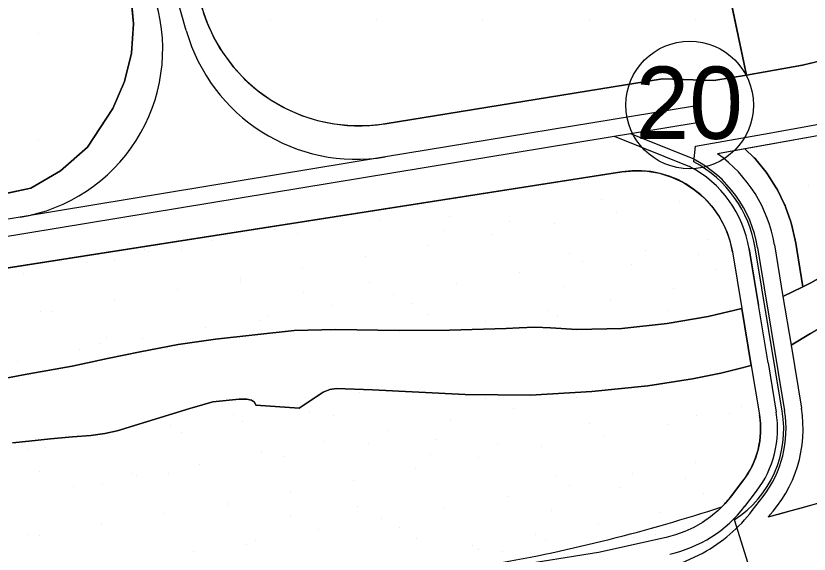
# Model space of a CAD drawing. Extents: x 419109 to 421295, y 4452223 to 4457798.
# Drawn here: x 420441.4 to 420628, y 4454862 to 4454988.5 of the extents above; entities that cross this region are included whole.
import ezdxf

# ---------------------------------------------------------------- set-up
doc = ezdxf.new("R2010")
doc.units = 0
for name, color, linetype in [('0_PLAN_ONAMA_İLAVE_SINIRI', 7, 'Continuous'), ('ADAKENARI', 7, 'Continuous'), ('Default', 7, 'Continuous'), ('KALDIRIM_FAT', 7, 'Continuous'), ('KD_DAIRE', 7, 'Continuous'), ('KD_YGEN', 7, 'Continuous'), ('PL_AYA_PARK_DINLENME', 7, 'Continuous'), ('PL_EĞİTİM', 7, 'Continuous'), ('PL_KAMU_HİZMET_ALANI', 7, 'Continuous'), ('PL_TA_K_DERE', 7, 'Continuous'), ('TR_PARKALANI', 7, 'Continuous'), ('TRFAT_EĞİTİM', 7, 'Continuous'), ('TRFAT_KHA', 7, 'Continuous'), ('TRFAT_PARKALANI', 7, 'Continuous')]:
    doc.layers.add(name, color=color, linetype=linetype)

# ---------------------------------------------------------------- blocks, each defined once
blk = doc.blocks.new('POINT_DISPLAY')
at = {"layer": 'Default'}
blk.add_line((0, 0), (0, 0), dxfattribs=at)

msp = doc.modelspace()

# ---------------------------------------------------------------- linework, layer by layer
at = {"layer": '0_PLAN_ONAMA_İLAVE_SINIRI'}
for p, q in [((420600.86, 4454954.21), (420601.25, 4454957.92)), ((420621.67, 4454895.6), (420615.32, 4454933.97))]:
    msp.add_line(p, q, dxfattribs=at)
for points in [[(420601.25, 4454957.92), (420617.24, 4454960.76), (420629.43, 4454962.93), (420641.15, 4454965.81), (420656.64, 4454970.34), (420670.84, 4454975.08), (420704.35, 4454989.38), (420859.78, 4455086.9)], [(420685.41, 4454871.37), (420616.78, 4454849.77), (420610.4, 4454870.05)]]:
    msp.add_lwpolyline(points, dxfattribs=at)
for centre, radius, start, end in [((420587.48, 4454929.36), 28.23, 9.3953, 61.6952), ((420596.52, 4454891.43), 25.49, 302.9728, 9.3953)]:
    msp.add_arc(centre, radius, start, end, dxfattribs=at)
at = {"layer": 'ADAKENARI'}
for p, q in [((420607.93, 4454999.82), (420613.29, 4454974.6)), ((420468.34, 4454994.88), (420469.12, 4454986.67)), ((420469.12, 4454986.67), (420468.62, 4454979.78)), ((420468.62, 4454979.78), (420466.97, 4454973.08)), ((420637.43, 4454979.63), (420626.47, 4454976.94)), ((420626.47, 4454976.94), (420613.29, 4454974.6)), ((420613.29, 4454974.6), (420605.56, 4454973.34)), ((420466.97, 4454973.08), (420464.21, 4454966.74)), ((420593.54, 4454973.74), (420528.25, 4454963.19)), ((420605.56, 4454973.34), (420593.54, 4454973.74)), ((420464.21, 4454966.74), (420458.28, 4454957.65)), ((420629.99, 4454960.3), (420606.43, 4454956.12)), ((420458.28, 4454957.65), (420451.94, 4454952.12)), ((420451.94, 4454952.12), (420444.92, 4454948.04)), ((420583.96, 4454951.88), (420334.51, 4454912.87)), ((420444.92, 4454948.04), (420432.46, 4454945.39)), ((420619.82, 4454934.71), (420621.84, 4454922.55)), ((420609.96, 4454933.08), (420612.16, 4454919.77)), ((420621.84, 4454922.55), (420623.73, 4454911.11)), ((420612.16, 4454919.77), (420604.23, 4454917.89)), ((420612.16, 4454919.77), (420614.39, 4454906.31)), ((420604.23, 4454917.89), (420594.61, 4454916.2)), ((420516.59, 4454914.79), (420506.84, 4454914.56)), ((420531.59, 4454914.58), (420516.59, 4454914.79)), ((420543.4, 4454914.67), (420531.59, 4454914.58)), ((420556.71, 4454915.05), (420543.4, 4454914.67)), ((420559.81, 4454915.21), (420556.71, 4454915.05)), ((420563.45, 4454915.36), (420559.81, 4454915.21)), ((420567.17, 4454915.16), (420563.45, 4454915.36)), ((420573.35, 4454914.83), (420567.17, 4454915.16)), ((420583.92, 4454915.01), (420573.35, 4454914.83)), ((420594.61, 4454916.2), (420583.92, 4454915.01)), ((420497.6, 4454913.58), (420488.38, 4454912.51)), ((420506.84, 4454914.56), (420497.6, 4454913.58)), ((420479.58, 4454911.31), (420470.68, 4454909.58)), ((420488.38, 4454912.51), (420479.58, 4454911.31)), ((420470.68, 4454909.58), (420462.98, 4454907.99)), ((420462.98, 4454907.99), (420454.68, 4454906.21)), ((420454.68, 4454906.21), (420444.48, 4454904.37)), ((420607.24, 4454904.55), (420611.33, 4454905.54)), ((420611.33, 4454905.54), (420614.39, 4454906.31)), ((420614.39, 4454906.31), (420616.31, 4454894.71)), ((420444.48, 4454904.37), (420434.82, 4454902.57)), ((420600.57, 4454903.17), (420607.24, 4454904.55)), ((420590.06, 4454901.54), (420600.57, 4454903.17)), ((420508.07, 4454896.32), (420513.7, 4454900.11)), ((420513.7, 4454900.11), (420515.29, 4454900.67)), ((420515.29, 4454900.67), (420516.77, 4454900.97)), ((420516.77, 4454900.97), (420525.29, 4454900.59)), ((420525.29, 4454900.59), (420547.07, 4454899.51)), ((420562.48, 4454899.35), (420576.86, 4454900.22)), ((420576.86, 4454900.22), (420590.06, 4454901.54)), ((420493.96, 4454898.44), (420487.75, 4454897.77)), ((420495.72, 4454898.4), (420493.96, 4454898.44)), ((420496.85, 4454898.2), (420495.72, 4454898.4)), ((420497.52, 4454897.7), (420496.85, 4454898.2)), ((420547.07, 4454899.51), (420562.48, 4454899.35)), ((420482.34, 4454896.2), (420465.26, 4454891.02)), ((420485.29, 4454897.13), (420482.34, 4454896.2)), ((420487.75, 4454897.77), (420485.29, 4454897.13)), ((420497.88, 4454896.99), (420497.52, 4454897.7)), ((420497.88, 4454896.99), (420508.07, 4454896.32)), ((420462.34, 4454890.39), (420459.08, 4454889.91)), ((420465.26, 4454891.02), (420462.34, 4454890.39)), ((420444.45, 4454888.53), (420440.67, 4454888.18)), ((420449.56, 4454889.09), (420444.45, 4454888.53)), ((420454.78, 4454889.57), (420449.56, 4454889.09)), ((420459.08, 4454889.91), (420454.78, 4454889.57)), ((420609.7, 4454875.67), (420612.42, 4454879.21))]:
    msp.add_line(p, q, dxfattribs=at)
for points in [[(420621.84, 4454922.55), (420628.56, 4454925.86), (420634.25, 4454929.18), (420641.97, 4454934.05), (420649.52, 4454938.93), (420657.09, 4454943.66), (420664.37, 4454947.12), (420674.1, 4454951.98), (420684.83, 4454957.58), (420695.54, 4454963.42), (420710.33, 4454971.2), (420720.25, 4454976.21), (420730.84, 4454981.97), (420734.19, 4454983.6)], [(420734.09, 4454973.7), (420728.96, 4454971), (420717.53, 4454964.1), (420708.32, 4454959.17), (420701.31, 4454955.13), (420692.1, 4454949.99), (420677.13, 4454942.82), (420669.89, 4454939.02), (420661.92, 4454934.84), (420658.07, 4454932.57), (420650.04, 4454927.17), (420647.86, 4454926.01), (420645.27, 4454924.73), (420643.03, 4454923.25), (420636.33, 4454918.73), (420632.78, 4454916.48), (420623.73, 4454911.11)]]:
    msp.add_lwpolyline(points, dxfattribs=at)
for centre, radius, start, end in [((420522.12, 4455001.15), 38.45, 195.8222, 279.1801), ((420587.48, 4454929.36), 32.79, 9.3953, 54.6849), ((420587.48, 4454929.36), 22.79, 9.3953, 98.8885), ((420478.64, 4455402.72), 550, 284.7135, 303.5681), ((420596.52, 4454891.43), 30.05, 316.517, 9.3953), ((420596.52, 4454891.43), 20.05, 322.4521, 9.3953), ((420588.6, 4454891.89), 26.61, 315.1433, 322.4521), ((420485.85, 4455244.77), 391.05, 280.0279, 288.1197)]:
    msp.add_arc(centre, radius, start, end, dxfattribs=at)
at = {"layer": 'KALDIRIM_FAT'}
for p, q in [((420481.51, 4454985.08), (420475.08, 4455007.77)), ((420601.01, 4454967.34), (420528.32, 4454955.36)), ((420601.68, 4454963.4), (420403.27, 4454930.7)), ((420599.97, 4454953.07), (420582.25, 4454960.2)), ((420600.72, 4454954.92), (420586.05, 4454960.82)), ((420528.32, 4454955.36), (420442.42, 4454941.21)), ((420442.42, 4454941.21), (420393.37, 4454933.13)), ((420618.33, 4454906.96), (420613.9, 4454933.73)), ((420613.9, 4454933.73), (420616.11, 4454920.42)), ((420615.88, 4454934.06), (420622.23, 4454895.69)), ((420623.73, 4454911.11), (420626.17, 4454896.34)), ((420618.33, 4454906.96), (420620.25, 4454895.36)), ((420612.87, 4454873.23), (420615.59, 4454876.78)), ((420614.63, 4454872.24), (420617.18, 4454875.56)), ((420603.05, 4454862.26), (420594.74, 4454858.37))]:
    msp.add_line(p, q, dxfattribs=at)
for centre, radius, start, end in [((420435.91, 4454980.73), 40.06, 279.3573, 15.8222), ((420521.55, 4454996.43), 41.62, 195.8222, 279.3573), ((420587.48, 4454929.36), 28.79, 9.3953, 62.6166), ((420587.48, 4454929.36), 26.79, 9.3953, 62.4157), ((420596.52, 4454891.43), 24.05, 322.4521, 9.3953), ((420596.52, 4454891.43), 26.05, 322.4521, 9.3953), ((420588.6, 4454891.89), 30.61, 282.4712, 322.4521), ((420584.76, 4454895.2), 37.67, 299.0511, 322.4521)]:
    msp.add_arc(centre, radius, start, end, dxfattribs=at)
at = {"layer": 'KD_DAIRE'}
msp.add_circle((420599.91, 4454967.57), 15, dxfattribs=at)
at = {"layer": 'PL_AYA_PARK_DINLENME'}
for p, q in [((420629.99, 4454960.3), (420612.9, 4454957.26)), ((420612.9, 4454957.26), (420606.43, 4454956.12)), ((420619.82, 4454934.71), (420621.84, 4454922.55)), ((420621.84, 4454922.55), (420626.52, 4454924.86)), ((420628.34, 4454913.85), (420623.73, 4454911.11)), ((420623.73, 4454911.11), (420626.17, 4454896.34))]:
    msp.add_line(p, q, dxfattribs=at)
for points in [[(420626.52, 4454924.86), (420628.56, 4454925.86), (420634.25, 4454929.18), (420641.97, 4454934.05), (420649.52, 4454938.93), (420657.09, 4454943.66), (420664.37, 4454947.12), (420674.1, 4454951.98), (420684.83, 4454957.58), (420695.54, 4454963.42), (420710.33, 4454971.2), (420720.25, 4454976.21), (420730.84, 4454981.97), (420734.19, 4454983.6)], [(420612.9, 4454957.26), (420615.06, 4454955.18), (420615.27, 4454954.97), (420615.46, 4454954.75), (420617.87, 4454951.81), (420618.05, 4454951.58), (420618.21, 4454951.34), (420620.26, 4454948.13), (420620.42, 4454947.89), (420620.55, 4454947.63), (420622.22, 4454944.21), (420622.34, 4454943.95), (420622.44, 4454943.67), (420623.7, 4454940.08), (420623.8, 4454939.81), (420623.86, 4454939.53), (420624.7, 4454935.82), (420624.73, 4454935.67), (420624.76, 4454935.53), (420626.52, 4454924.86)], [(420626.52, 4454924.86), (420624.76, 4454935.53), (420624.73, 4454935.67), (420624.7, 4454935.82), (420623.86, 4454939.53), (420623.8, 4454939.81), (420623.7, 4454940.08), (420622.44, 4454943.67), (420622.34, 4454943.95), (420622.22, 4454944.21), (420620.55, 4454947.63), (420620.42, 4454947.89), (420620.26, 4454948.13), (420618.21, 4454951.34), (420618.05, 4454951.58), (420617.87, 4454951.81), (420615.46, 4454954.75), (420615.27, 4454954.97), (420615.06, 4454955.18), (420612.9, 4454957.26)], [(420334.51, 4454912.87), (420583.96, 4454951.88), (420586.91, 4454952.14), (420589.87, 4454952.02), (420592.79, 4454951.52), (420595.62, 4454950.64), (420598.31, 4454949.41), (420600.82, 4454947.83), (420603.11, 4454945.94), (420605.13, 4454943.77), (420606.85, 4454941.36), (420608.24, 4454938.74), (420609.28, 4454935.97), (420609.96, 4454933.08), (420612.16, 4454919.77), (420604.23, 4454917.89), (420594.61, 4454916.2), (420583.92, 4454915.01), (420573.35, 4454914.83), (420567.17, 4454915.16), (420563.45, 4454915.36), (420559.81, 4454915.21), (420556.71, 4454915.05), (420543.4, 4454914.67), (420531.59, 4454914.58), (420516.59, 4454914.79), (420506.84, 4454914.56), (420497.6, 4454913.58), (420488.38, 4454912.51), (420479.58, 4454911.31), (420470.68, 4454909.58), (420462.98, 4454907.99), (420454.68, 4454906.21), (420444.48, 4454904.37), (420434.82, 4454902.57)], [(420440.67, 4454888.18), (420444.45, 4454888.53), (420449.56, 4454889.09), (420454.78, 4454889.57), (420459.08, 4454889.91), (420462.34, 4454890.39), (420465.26, 4454891.02), (420482.34, 4454896.2), (420485.29, 4454897.13), (420487.75, 4454897.77), (420493.96, 4454898.44), (420495.72, 4454898.4), (420496.85, 4454898.2), (420497.52, 4454897.7), (420497.88, 4454896.99), (420508.07, 4454896.32), (420513.7, 4454900.11), (420515.29, 4454900.67), (420516.77, 4454900.97), (420525.29, 4454900.59), (420547.07, 4454899.51), (420562.48, 4454899.35), (420576.86, 4454900.22), (420590.06, 4454901.54), (420600.57, 4454903.17), (420607.24, 4454904.55), (420611.33, 4454905.54), (420614.39, 4454906.31), (420616.31, 4454894.71), (420616.54, 4454892.67), (420616.56, 4454890.62), (420616.37, 4454888.57), (420615.97, 4454886.56), (420615.37, 4454884.59), (420614.58, 4454882.7), (420613.59, 4454880.9), (420612.42, 4454879.21), (420609.7, 4454875.67), (420608.21, 4454873.89), (420606.56, 4454872.25), (420604.78, 4454870.76), (420602.88, 4454869.43), (420600.87, 4454868.27), (420598.77, 4454867.3), (420596.59, 4454866.5), (420594.34, 4454865.9), (420578.43, 4454862.38), (420343.8, 4454824.92)]]:
    msp.add_lwpolyline(points, dxfattribs=at)
for centre, radius, start, end in [((420587.48, 4454929.36), 32.79, 9.3953, 54.6849), ((420478.64, 4455402.72), 550, 284.7135, 297.5723), ((420596.52, 4454891.43), 30.05, 316.517, 9.3953)]:
    msp.add_arc(centre, radius, start, end, dxfattribs=at)
at = {"layer": 'PL_EĞİTİM'}
msp.add_lwpolyline([(420345.26, 4455009.14), (420345.72, 4454934.33), (420368.62, 4454935.68), (420391.72, 4454939.02), (420432.46, 4454945.39), (420444.92, 4454948.04), (420451.94, 4454952.12), (420458.28, 4454957.65), (420464.21, 4454966.74), (420466.97, 4454973.08), (420468.62, 4454979.78), (420469.12, 4454986.67), (420468.34, 4454994.88), (420464.66, 4455007.88)], dxfattribs=at)
at = {"layer": 'PL_KAMU_HİZMET_ALANI'}
for points in [[(420480.29, 4455007.71), (420485.12, 4454990.66), (420486.41, 4454986.88), (420488.08, 4454983.25), (420490.12, 4454979.82), (420492.51, 4454976.62), (420495.21, 4454973.68), (420498.21, 4454971.03), (420501.46, 4454968.72), (420504.93, 4454966.75), (420508.6, 4454965.15), (420512.4, 4454963.94), (420516.31, 4454963.14), (420520.29, 4454962.74), (420524.28, 4454962.76), (420528.25, 4454963.19), (420593.54, 4454973.74), (420605.56, 4454973.34), (420613.29, 4454974.6), (420607.93, 4454999.82), (420608.01, 4455006.36)], [(420608.01, 4455006.36), (420607.93, 4454999.82), (420613.29, 4454974.6), (420626.47, 4454976.94), (420637.43, 4454979.63), (420652.36, 4454984), (420665.76, 4454988.47), (420705.27, 4455005.33)]]:
    msp.add_lwpolyline(points, dxfattribs=at)
at = {"layer": 'PL_TA_K_DERE'}
for p, q in [((420626.52, 4454924.86), (420621.84, 4454922.55)), ((420621.84, 4454922.55), (420623.73, 4454911.11)), ((420623.73, 4454911.11), (420628.34, 4454913.85))]:
    msp.add_line(p, q, dxfattribs=at)
for points in [[(420641.97, 4454934.05), (420634.25, 4454929.18), (420628.56, 4454925.86), (420626.52, 4454924.86)], [(420440.67, 4454888.18), (420444.45, 4454888.53), (420449.56, 4454889.09), (420454.78, 4454889.57), (420459.08, 4454889.91), (420462.34, 4454890.39), (420465.26, 4454891.02), (420482.34, 4454896.2), (420485.29, 4454897.13), (420487.75, 4454897.77), (420493.96, 4454898.44), (420495.72, 4454898.4), (420496.85, 4454898.2), (420497.52, 4454897.7), (420497.88, 4454896.99), (420508.07, 4454896.32), (420513.7, 4454900.11), (420515.29, 4454900.67), (420516.77, 4454900.97), (420525.29, 4454900.59), (420547.07, 4454899.51), (420562.48, 4454899.35), (420576.86, 4454900.22), (420590.06, 4454901.54), (420600.57, 4454903.17), (420607.24, 4454904.55), (420611.33, 4454905.54), (420614.39, 4454906.31), (420612.16, 4454919.77), (420604.23, 4454917.89), (420594.61, 4454916.2), (420583.92, 4454915.01), (420573.35, 4454914.83), (420567.17, 4454915.16), (420563.45, 4454915.36), (420559.81, 4454915.21), (420556.71, 4454915.05), (420543.4, 4454914.67), (420531.59, 4454914.58), (420516.59, 4454914.79), (420506.84, 4454914.56), (420497.6, 4454913.58), (420488.38, 4454912.51), (420479.58, 4454911.31), (420470.68, 4454909.58), (420462.98, 4454907.99), (420454.68, 4454906.21), (420444.48, 4454904.37), (420434.82, 4454902.57)], [(420434.82, 4454902.57), (420444.48, 4454904.37), (420454.68, 4454906.21), (420462.98, 4454907.99), (420470.68, 4454909.58), (420479.58, 4454911.31), (420488.38, 4454912.51), (420497.6, 4454913.58), (420506.84, 4454914.56), (420516.59, 4454914.79), (420531.59, 4454914.58), (420543.4, 4454914.67), (420556.71, 4454915.05), (420559.81, 4454915.21), (420563.45, 4454915.36), (420567.17, 4454915.16), (420573.35, 4454914.83), (420583.92, 4454915.01), (420594.61, 4454916.2), (420604.23, 4454917.89), (420612.16, 4454919.77), (420614.39, 4454906.31), (420611.33, 4454905.54), (420607.24, 4454904.55), (420600.57, 4454903.17), (420590.06, 4454901.54), (420576.86, 4454900.22), (420562.48, 4454899.35), (420547.07, 4454899.51), (420525.29, 4454900.59), (420516.77, 4454900.97), (420515.29, 4454900.67), (420513.7, 4454900.11), (420508.07, 4454896.32), (420497.88, 4454896.99), (420497.52, 4454897.7), (420496.85, 4454898.2), (420495.72, 4454898.4), (420493.96, 4454898.44), (420487.75, 4454897.77), (420485.29, 4454897.13), (420482.34, 4454896.2), (420465.26, 4454891.02), (420462.34, 4454890.39), (420459.08, 4454889.91), (420454.78, 4454889.57), (420449.56, 4454889.09), (420444.45, 4454888.53), (420440.67, 4454888.18)]]:
    msp.add_lwpolyline(points, dxfattribs=at)
at = {"layer": 'TRFAT_EĞİTİM'}
for p, q in [((420446.71, 4454984.33), (420446.71, 4454984.33)), ((420446.71, 4454959.33), (420446.71, 4454959.33))]:
    msp.add_line(p, q, dxfattribs=at)
at = {"layer": 'TRFAT_KHA'}
for p, q in [((420501.28, 4454987.74), (420501.28, 4454987.74)), ((420526.28, 4454987.74), (420526.28, 4454987.74)), ((420551.28, 4454987.74), (420551.28, 4454987.74)), ((420576.28, 4454987.74), (420576.28, 4454987.74)), ((420601.28, 4454987.74), (420601.28, 4454987.74))]:
    msp.add_line(p, q, dxfattribs=at)
at = {"layer": 'TRFAT_PARKALANI'}
for p, q in [((420579.24, 4454945.39), (420579.24, 4454945.39)), ((420597.55, 4454945.01), (420597.55, 4454945.01)), ((420531.8, 4454943.57), (420531.8, 4454943.57)), ((420517.03, 4454940.97), (420517.03, 4454940.97)), ((420543.4, 4454941.43), (420543.4, 4454941.43)), ((420582.77, 4454942.41), (420582.77, 4454942.41)), ((420527.21, 4454940.56), (420527.21, 4454940.56)), ((420557.62, 4454940.28), (420557.62, 4454940.28)), ((420568, 4454939.8), (420568, 4454939.8)), ((420502.25, 4454938.36), (420502.25, 4454938.36)), ((420507.57, 4454937.47), (420507.57, 4454937.47)), ((420541.98, 4454937.96), (420541.98, 4454937.96)), ((420553.23, 4454937.2), (420553.23, 4454937.2)), ((420487.48, 4454935.76), (420487.48, 4454935.76)), ((420604.21, 4454936.03), (420604.21, 4454936.03)), ((420471.73, 4454933.51), (420471.73, 4454933.51)), ((420480.29, 4454933.61), (420480.29, 4454933.61)), ((420538.46, 4454934.59), (420538.46, 4454934.59)), ((420589.43, 4454933.43), (420589.43, 4454933.43)), ((420472.71, 4454933.15), (420472.71, 4454933.15)), ((420523.69, 4454931.99), (420523.69, 4454931.99)), ((420571.53, 4454932.75), (420571.53, 4454932.75)), ((420601.94, 4454932.47), (420601.94, 4454932.47)), ((420457.94, 4454930.55), (420457.94, 4454930.55)), ((420464.65, 4454931.29), (420464.65, 4454931.29)), ((420574.66, 4454930.82), (420574.66, 4454930.82)), ((420586.3, 4454930.15), (420586.3, 4454930.15)), ((420443.16, 4454927.95), (420443.16, 4454927.95)), ((420508.91, 4454929.38), (420508.91, 4454929.38)), ((420559.89, 4454928.22), (420559.89, 4454928.22)), ((420606.18, 4454928.84), (420606.18, 4454928.84)), ((420494.14, 4454926.78), (420494.14, 4454926.78)), ((420494.19, 4454926.08), (420494.19, 4454926.08)), ((420610.87, 4454927.05), (420610.87, 4454927.05)), ((420479.37, 4454924.18), (420479.37, 4454924.18)), ((420524.61, 4454925.79), (420524.61, 4454925.79)), ((420545.12, 4454925.61), (420545.12, 4454925.61)), ((420570.35, 4454924.88), (420570.35, 4454924.88)), ((420596.1, 4454924.45), (420596.1, 4454924.45)), ((420508.97, 4454923.47), (420508.97, 4454923.47)), ((420530.35, 4454923.01), (420530.35, 4454923.01)), ((420464.6, 4454921.57), (420464.6, 4454921.57)), ((420515.57, 4454920.4), (420515.57, 4454920.4)), ((420534.51, 4454920.92), (420534.51, 4454920.92)), ((420581.32, 4454921.84), (420581.32, 4454921.84)), ((420447.27, 4454919.12), (420447.27, 4454919.12)), ((420449.83, 4454918.97), (420449.83, 4454918.97)), ((420566.55, 4454919.24), (420566.55, 4454919.24)), ((420594.69, 4454919.2), (420594.69, 4454919.2)), ((420498.67, 4454916.95), (420498.67, 4454916.95)), ((420500.8, 4454917.8), (420500.8, 4454917.8)), ((420538.51, 4454918.26), (420538.51, 4454918.26)), ((420551.78, 4454916.63), (420551.78, 4454916.63)), ((420568.92, 4454917.98), (420568.92, 4454917.98)), ((420486.03, 4454915.2), (420486.03, 4454915.2)), ((420553.28, 4454915.66), (420553.28, 4454915.66)), ((420558.86, 4454915.24), (420558.86, 4454915.24)), ((420462.84, 4454912.99), (420462.84, 4454912.99)), ((420461.18, 4454911.59), (420461.18, 4454911.59)), ((420471.26, 4454912.59), (420471.26, 4454912.59)), ((420456.49, 4454909.99), (420456.49, 4454909.99)), ((420441.71, 4454907.38), (420441.71, 4454907.38)), ((420522.2, 4454899.97), (420522.2, 4454899.97)), ((420572.06, 4454899.87), (420572.06, 4454899.87)), ((420551.95, 4454898.5), (420551.95, 4454898.5)), ((420573.17, 4454898.81), (420573.17, 4454898.81)), ((420558.4, 4454896.2), (420558.4, 4454896.2)), ((420612.14, 4454896.78), (420612.14, 4454896.78)), ((420492.65, 4454894.77), (420492.65, 4454894.77)), ((420510.37, 4454895.51), (420510.37, 4454895.51)), ((420516.12, 4454894.53), (420516.12, 4454894.53)), ((420601.6, 4454894.66), (420601.6, 4454894.66)), ((420609.38, 4454895.04), (420609.38, 4454895.04)), ((420494.73, 4454893.2), (420494.73, 4454893.2)), ((420543.63, 4454893.6), (420543.63, 4454893.6)), ((420576.3, 4454892.82), (420576.3, 4454892.82)), ((420594.61, 4454892.43), (420594.61, 4454892.43)), ((420477.88, 4454892.16), (420477.88, 4454892.16)), ((420480.28, 4454890.57), (420480.28, 4454890.57)), ((420528.86, 4454891), (420528.86, 4454891)), ((420616.38, 4454892.05), (420616.38, 4454892.05)), ((420463.11, 4454889.56), (420463.11, 4454889.56)), ((420540.46, 4454888.85), (420540.46, 4454888.85)), ((420579.83, 4454889.83), (420579.83, 4454889.83)), ((420448.34, 4454886.95), (420448.34, 4454886.95)), ((420514.08, 4454888.39), (420514.08, 4454888.39)), ((420524.27, 4454887.99), (420524.27, 4454887.99)), ((420554.68, 4454887.7), (420554.68, 4454887.7)), ((420565.06, 4454887.22), (420565.06, 4454887.22)), ((420444.44, 4454886.61), (420444.44, 4454886.61)), ((420499.31, 4454885.79), (420499.31, 4454885.79)), ((420504.63, 4454884.89), (420504.63, 4454884.89)), ((420539.04, 4454885.38), (420539.04, 4454885.38)), ((420484.54, 4454883.18), (420484.54, 4454883.18)), ((420550.29, 4454884.62), (420550.29, 4454884.62)), ((420601.27, 4454883.45), (420601.27, 4454883.45)), ((420446.94, 4454881.31), (420446.94, 4454881.31)), ((420535.52, 4454882.02), (420535.52, 4454882.02)), ((420468.79, 4454880.93), (420468.79, 4454880.93)), ((420469.77, 4454880.58), (420469.77, 4454880.58)), ((420477.35, 4454881.03), (420477.35, 4454881.03)), ((420520.74, 4454879.41), (420520.74, 4454879.41)), ((420568.59, 4454880.17), (420568.59, 4454880.17)), ((420586.49, 4454880.85), (420586.49, 4454880.85)), ((420599, 4454879.89), (420599, 4454879.89)), ((420455, 4454877.97), (420455, 4454877.97)), ((420461.71, 4454878.71), (420461.71, 4454878.71)), ((420571.72, 4454878.24), (420571.72, 4454878.24)), ((420583.36, 4454877.57), (420583.36, 4454877.57)), ((420505.97, 4454876.81), (420505.97, 4454876.81)), ((420556.95, 4454875.64), (420556.95, 4454875.64)), ((420603.24, 4454876.26), (420603.24, 4454876.26)), ((420491.2, 4454874.2), (420491.2, 4454874.2)), ((420607.93, 4454874.47), (420607.93, 4454874.47)), ((420491.25, 4454873.5), (420491.25, 4454873.5)), ((420521.67, 4454873.21), (420521.67, 4454873.21)), ((420542.18, 4454873.04), (420542.18, 4454873.04)), ((420567.41, 4454872.3), (420567.41, 4454872.3)), ((420593.15, 4454871.87), (420593.15, 4454871.87)), ((420476.43, 4454871.6), (420476.43, 4454871.6)), ((420506.02, 4454870.89), (420506.02, 4454870.89)), ((420527.41, 4454870.43), (420527.41, 4454870.43)), ((420461.66, 4454868.99), (420461.66, 4454868.99)), ((420531.57, 4454868.34), (420531.57, 4454868.34)), ((420578.38, 4454869.27), (420578.38, 4454869.27)), ((420444.33, 4454866.54), (420444.33, 4454866.54)), ((420446.88, 4454866.39), (420446.88, 4454866.39)), ((420512.63, 4454867.83), (420512.63, 4454867.83)), ((420563.61, 4454866.66), (420563.61, 4454866.66)), ((420591.75, 4454866.62), (420591.75, 4454866.62)), ((420495.73, 4454864.37), (420495.73, 4454864.37)), ((420497.86, 4454865.22), (420497.86, 4454865.22)), ((420535.57, 4454865.69), (420535.57, 4454865.69)), ((420565.98, 4454865.4), (420565.98, 4454865.4)), ((420483.09, 4454862.62), (420483.09, 4454862.62)), ((420548.84, 4454864.06), (420548.84, 4454864.06)), ((420550.34, 4454863.08), (420550.34, 4454863.08)), ((420555.92, 4454862.66), (420555.92, 4454862.66))]:
    msp.add_line(p, q, dxfattribs=at)

# ---------------------------------------------------------------- block references
at = {"layer": 'TR_PARKALANI', "xscale": 0.1, "yscale": 0.10000000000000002}
for p in [(420621.19, 4454957.63), (420627.85, 4454948.65), (420618.06, 4454943.93), (420619.74, 4454937.06)]:
    msp.add_blockref('POINT_DISPLAY', p, dxfattribs=at)

# ---------------------------------------------------------------- texts
at = {"layer": 'KD_YGEN'}
msp.add_text('20', height=17, dxfattribs=at).set_placement((420587.14, 4454959.61))

doc.saveas('drawing.dxf')
